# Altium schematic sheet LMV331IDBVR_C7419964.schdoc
size 127 x 101 mm
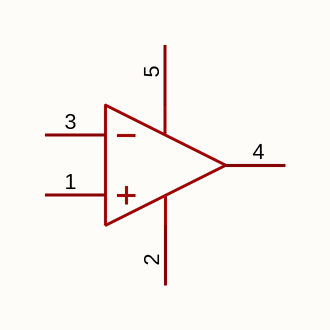
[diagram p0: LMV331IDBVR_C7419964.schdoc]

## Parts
U?  lmv331idbvr_c7419964  [SOT-23-5_L3.0-W1.6-P0.95-LS2.8-BR]  (value not drawn)

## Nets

Not connected (* = marked no-connect by the designer): U? 1(IN+) 2(GND) 3(IN-) 4(OUT) 5(VDD)

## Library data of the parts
U? = lmv331idbvr_c7419964: 比较器数:单路;输入失调电压(Vos):500uV;输入偏置电流(Ib):6pA;轨到轨:轨到轨输入;; Manufacturer: TECH PUBLIC(台舟); AddInBom: yes; ModelId: 72410e292833493f86746b22636ce101; ModelTransform: 110.236,116.1415,0,0,0,0,0.002,0.001,0; Number of Channels: 单路; Vos - Input Offset Voltage: 500uV; Ib - Input Bias Current: 6pA; Propagation Delay Time: 77.5ns; Input Hysteresis Voltage (Vhys): 6mV; Common Mode Rejection Ratio(CMRR): 70dB; Output Type: 开漏; Output Mode: CMOS；TTL; Rail to Rail: 轨到轨输入; Quiescent Current: 40uA; Maximum Power Supply Range (Vdd-Vss): 7V; Single Supply: 1.8V~5.5V; Dual Supply: 0.9V~2.75V；-2.75V~-0.9V; Input Offset Voltage Drift(Vos TC): 2uV/℃; Input Offset Current(Ios): 4pA; Response Time (tr): 5ns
